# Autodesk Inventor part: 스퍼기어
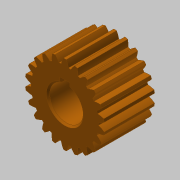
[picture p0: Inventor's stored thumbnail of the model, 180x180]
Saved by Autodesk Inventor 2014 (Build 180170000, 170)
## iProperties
Created: 2019-03
Part Number: 스퍼기어
Material: 강철
Document SubType Name: Modeling
Designer: mduedu
Categories: <?xml version="1.0" encoding="UTF-16"?> <MemberInstance><Categories><FamilyTemplate><FamilyTemplateParameter ValueType="xs:double" Id="1" ObjectReferenceKey="da
Density: 1 g/cm^3
Appearance: 주황색
CustomPartVersion: 1
Author: mduedu
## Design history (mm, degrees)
sketch "Sketch1"
  geometry: C1 r 23.6 at (0, 0)
  constraints: 1 centre point
  dimensions: "d0" = 47.2 diameter of C1 (= da_da)
extrude "Extrusion1" new body sketch "Sketch1" distance "d1" = 30 (= da_b); taper "d2" = 0 deg
workplane "Work Plane2"
sketch "Sketch2"
  geometry: C1 r 23.6 at (0, 0) reference; C2 r 22 at (0, 0)
  constraints: 1 centre point, 1 coincident
  dimensions: "d3" = 44 diameter of C2 (= da_dw)
feature "피치 지름" sketch "Sketch2" dims "d4" = 10, "d5" = 0
workplane "Work Plane8"
workplane "Work Plane9"
feature "스퍼 기어" dims "da_b" = 30, "da_d" = 44, "da_aw" = 44, "da_da" = 47.2, "da_df" = 40.172, "da_dw" = 44, angle "da_beta" = 0 deg, "da_lefttooth" = 0, "da_righttooth" = 0
sketch "스케치3"
  geometry: L1 (-3, 9.539)-(3, 9.539); L2 (3, 9.539)-(3, 12.8); L3 (3, 12.8)-(-3, 12.8); L4 (-3, 12.8)-(-3, 9.539); A1 r 10 centre (0, 0) between (-3, 9.539) and (3, 9.539); 1 further point
  constraints: 8 end point, 2 parallel, 2 point on circle, 1 centre point, 1 coincident, 1 horizontal, 1 perpendicular
  dimensions: "d49" = 20 diameter of A1; "d50" = 6 distance of L2.end L3.end; "d51" = 22.8 dimension on A1 L3
extrude "돌출2" cut sketch "스케치3" stored distance "d52" = 10; taper "d53" = 0 deg
chamfer "모따기1" distance "d54" = 1; stored, may be unused: second distance "d55" = 2, angle "d56" = 45 deg
body "Solid1"
body "Srf1"
other parameters: "d16" = 44 (= da_aw), "d17" = 0, "d34" = 1.428 (computed from da_z), "d39" = 0, "d41" = 0, "d43" = 44 (= da_aw), "d46" = 44 (= da_aw), "d47" = 0, "d48" = 0
